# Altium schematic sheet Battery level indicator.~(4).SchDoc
size A3; SheetNumber: 3; SheetTotal: 3
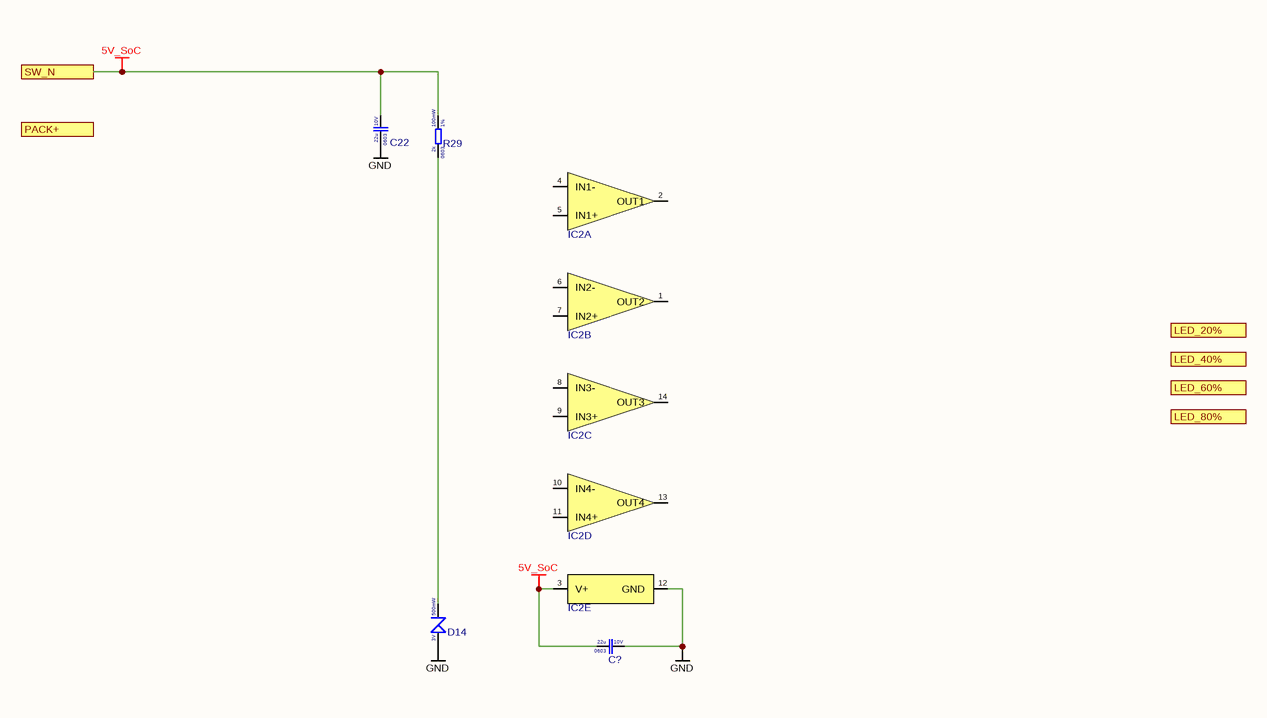
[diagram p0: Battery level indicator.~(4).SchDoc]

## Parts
C22  Voltage Rating: 10V  Case Code (Imperial): 0603  Capacitance: 22u  [CAP 0603]  (hidden comment: CGA0603X5R226M100JT)
C?  Voltage Rating: 10V  Case Code (Imperial): 0603  Capacitance: 22u  [CAP 0603]  (hidden comment: CGA0603X5R226M100JT)
D14  Power Rating: 500mW  Reverse Voltage: 3V  [SOD-123]  (hidden comment: BZT52C3V0)
IC2  LM339LVPWR  [TSSOP-14]  (value not drawn)  (parts A,B,C,D,E of 5)
R29  Resistance Tolerance: 1%  Resistance: 2k  Power Rating: 100mW  Case Code (Imperial): 0603  [RES_0603]  (hidden comment: 0603WAF2001T5E)

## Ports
LED_20% (see Arhitecture[8C]), LED_40% (see Arhitecture[8C]), LED_60% (see Arhitecture[8C]), LED_80% (see Arhitecture[8D]), PACK+ (see Arhitecture[7C], Charger[8A]), SW_N (see Arhitecture[7D])

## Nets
5V_SoC: C22.2 C?.1 IC2.3(V+) R29.2 ; port SW_N
GND: C22.1 C?.2 D14.A IC2.12(GND)
NetD14_K: D14.K R29.1

Not connected (* = marked no-connect by the designer): IC2 1(OUT2) 2(OUT1) 4(IN1-) 5(IN1+) 6(IN2-) 7(IN2+) 8(IN3-) 9(IN3+) 10(IN4-) 11(IN4+) 13(OUT4) 14(OUT3)

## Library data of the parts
C22 C? = CGA0603X5R226M100JT: Cap 22uF 10V 0603 X5R; Manufacturer: HRE
D14 = BZT52C3V0: Zener 3.0V 500mW SOD-123; Manufacturer: Shandong Jingdao Microelectronics
IC2 = LM339LVPWR: Comparator Quad 1.65~5.5V TSSOP-14; Manufacturer: Texas Instruments
R29 = 0603WAF2001T5E: Res 2k 0603 1% 100mW 75V; Manufacturer: Uni-Royal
